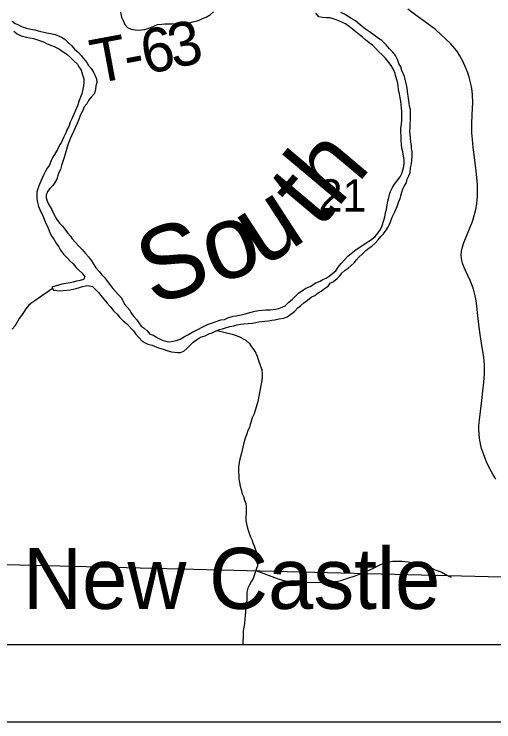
# Model space of a CAD drawing. Extents: x -7.9 to 76.1, y 0 to 22.
# Drawn here: x 7.274 to 7.895, y 14 to 14.915 of the extents above; entities that cross this region are included whole.
import ezdxf

# ---------------------------------------------------------------- set-up
doc = ezdxf.new("R2010")
doc.units = 0
for name, color, linetype in [('GM_X_Major_River', 7, 'Continuous'), ('GM_X_Major_River_Text', 7, 'Continuous'), ('GM_X_Minor_River', 7, 'Continuous'), ('GM_X_Section', 7, 'Continuous'), ('GM_X_Section_Text', 7, 'Continuous'), ('GM_X_State_Route', 7, 'Continuous'), ('GM_X_Township_Road_Text', 7, 'Continuous'), ('GM_X_Unincorporated_Text', 7, 'Continuous'), ('SC_Scratch1', 7, 'Continuous'), ('SH_Data', 7, 'Continuous')]:
    doc.layers.add(name, color=color, linetype=linetype)

msp = doc.modelspace()

# ---------------------------------------------------------------- linework, layer by layer
at = {"layer": 'GM_X_Major_River'}
for points in [[(7.6757, 14.56021), (7.68021, 14.56331), (7.68281, 14.56714), (7.68733, 14.56948), (7.69183, 14.57334), (7.69558, 14.5768), (7.69856, 14.58064), (7.7023, 14.58411), (7.70606, 14.58681), (7.71018, 14.59029), (7.71393, 14.59376), (7.71691, 14.59759), (7.72065, 14.60144), (7.7244, 14.60491), (7.72926, 14.60952), (7.73301, 14.61261), (7.73677, 14.61532), (7.74164, 14.61956), (7.745, 14.6234), (7.74836, 14.62762), (7.7521, 14.63109), (7.75545, 14.63569), (7.75842, 14.64067), (7.761, 14.64639), (7.76283, 14.65135), (7.76467, 14.65517), (7.76651, 14.65937), (7.76945, 14.66662), (7.77202, 14.67273), (7.77348, 14.67655), (7.77457, 14.68036), (7.77565, 14.68493), (7.77711, 14.68912), (7.77895, 14.69294), (7.78154, 14.69753), (7.78262, 14.70172), (7.78484, 14.70592), (7.7863, 14.7105), (7.78698, 14.7162), (7.78804, 14.72153), (7.78874, 14.72647), (7.78904, 14.73179), (7.78897, 14.7371), (7.78816, 14.74126), (7.7881, 14.74543), (7.78728, 14.74998), (7.78684, 14.7549), (7.78596, 14.76362), (7.78628, 14.76818), (7.78659, 14.77349), (7.78691, 14.77767), (7.78672, 14.79171), (7.78552, 14.79625), (7.78509, 14.80042), (7.78425, 14.80648), (7.78341, 14.81178), (7.78299, 14.81557), (7.78256, 14.81935), (7.78174, 14.8239), (7.77894, 14.83448), (7.77737, 14.83826), (7.7758, 14.84241), (7.77422, 14.84694), (7.77188, 14.85146), (7.7703, 14.85637), (7.76758, 14.86165), (7.76411, 14.86577), (7.75988, 14.87027), (7.75526, 14.87552), (7.74987, 14.88113), (7.74529, 14.88373), (7.74145, 14.88671), (7.73532, 14.89156), (7.73112, 14.89416), (7.72691, 14.89713), (7.7223, 14.90086), (7.71578, 14.90647), (7.7112, 14.90906), (7.70164, 14.915), (7.69668, 14.9172)], [(7.70585, 14.60199), (7.71673, 14.61087), (7.72913, 14.61901), (7.73289, 14.62172), (7.73666, 14.62367), (7.74116, 14.62753), (7.74451, 14.63175), (7.74711, 14.63558), (7.74934, 14.6394), (7.75298, 14.65008), (7.75406, 14.65465), (7.75476, 14.65883), (7.75585, 14.66264), (7.7569, 14.66873), (7.7576, 14.67329), (7.75867, 14.67824), (7.75976, 14.68205), (7.76122, 14.68586), (7.76381, 14.69083), (7.76641, 14.69542), (7.76939, 14.69926), (7.77348, 14.70463), (7.7757, 14.70921), (7.77678, 14.7134), (7.77823, 14.71798), (7.77855, 14.72291), (7.77887, 14.72709), (7.77767, 14.73163), (7.77684, 14.73693), (7.77564, 14.74184), (7.77474, 14.75208), (7.77453, 14.76763), (7.77522, 14.77258), (7.77553, 14.77789), (7.77585, 14.78245), (7.77576, 14.78928), (7.77532, 14.79383), (7.77489, 14.79762), (7.77444, 14.80254), (7.77362, 14.80709), (7.7728, 14.81201), (7.77158, 14.81768), (7.77115, 14.82185), (7.77033, 14.82601), (7.76914, 14.83017), (7.76794, 14.83471), (7.76713, 14.83849), (7.76479, 14.84339), (7.76206, 14.84867), (7.75897, 14.8528), (7.75435, 14.85805), (7.75051, 14.86217), (7.74551, 14.86703), (7.74166, 14.87115), (7.73782, 14.87489), (7.73361, 14.87825), (7.72863, 14.88198), (7.72479, 14.88534), (7.72096, 14.88832), (7.71674, 14.89168), (7.71176, 14.89578), (7.70754, 14.89914), (7.70294, 14.90249), (7.69875, 14.90433), (7.69493, 14.90618), (7.69074, 14.90763), (7.68693, 14.9091), (7.68237, 14.91017), (7.67819, 14.91049), (7.67288, 14.9108), (7.66831, 14.91188), (7.66446, 14.91638)], [(7.27139, 14.90601), (7.27522, 14.90302), (7.27979, 14.90119), (7.28361, 14.89935), (7.29009, 14.89716), (7.29579, 14.89572), (7.30073, 14.89503), (7.3053, 14.89357), (7.31595, 14.89106), (7.32127, 14.89), (7.32698, 14.88894), (7.33155, 14.88711), (7.33613, 14.88489), (7.33996, 14.88229), (7.34495, 14.8778), (7.34879, 14.87406), (7.35226, 14.86994), (7.35725, 14.86545), (7.36071, 14.8617), (7.3638, 14.85795), (7.36804, 14.8527), (7.37037, 14.84855), (7.37383, 14.84481), (7.37693, 14.83992), (7.38084, 14.83162), (7.3809, 14.82669), (7.37982, 14.8225), (7.37912, 14.81794), (7.37806, 14.81261), (7.37357, 14.80762), (7.37022, 14.8034), (7.368, 14.79919), (7.36464, 14.79535), (7.36355, 14.79154), (7.36133, 14.78772), (7.35948, 14.7839), (7.35766, 14.77894), (7.35545, 14.7736), (7.35287, 14.76825), (7.35066, 14.76328), (7.34846, 14.75794), (7.34661, 14.75412), (7.34405, 14.74764), (7.34187, 14.74002), (7.34006, 14.73392), (7.33824, 14.72858), (7.33715, 14.72477), (7.33533, 14.71943), (7.33388, 14.7141), (7.33204, 14.71028), (7.33057, 14.70647), (7.32912, 14.7019), (7.32652, 14.69731), (7.32392, 14.69348), (7.32018, 14.68963), (7.3172, 14.68579), (7.31537, 14.68122), (7.31542, 14.67742), (7.31698, 14.67365), (7.31856, 14.66949), (7.32282, 14.66272), (7.32479, 14.65744), (7.32711, 14.65368), (7.32944, 14.64953), (7.33254, 14.64464), (7.33676, 14.64091), (7.34371, 14.6319), (7.34679, 14.62815)], [(7.27345, 14.89313), (7.27805, 14.88978), (7.28302, 14.88719), (7.28949, 14.88539), (7.29442, 14.88469), (7.29899, 14.88362), (7.3028, 14.88253), (7.30699, 14.88108), (7.31194, 14.87925), (7.31576, 14.87702), (7.3211, 14.8752), (7.32567, 14.87336), (7.33255, 14.86966), (7.33637, 14.86706), (7.34211, 14.86334), (7.34709, 14.85924), (7.35171, 14.85437), (7.35593, 14.85063), (7.35788, 14.84687), (7.36059, 14.84273), (7.36256, 14.83669), (7.36415, 14.8314), (7.3642, 14.8276), (7.3639, 14.82228), (7.36281, 14.81809), (7.36176, 14.81201), (7.35808, 14.80361), (7.3559, 14.79675), (7.35296, 14.7895), (7.35039, 14.78377), (7.34854, 14.77995), (7.34671, 14.77537), (7.34488, 14.77004), (7.34266, 14.76621), (7.34119, 14.7624), (7.33824, 14.75628), (7.3353, 14.74979), (7.3327, 14.74558), (7.33012, 14.74023), (7.32752, 14.73564), (7.32418, 14.73029), (7.32197, 14.72608), (7.31977, 14.71998), (7.3168, 14.71576), (7.31457, 14.71194), (7.31235, 14.70773), (7.30977, 14.70239), (7.3061, 14.69323), (7.30464, 14.68904), (7.30356, 14.68523), (7.30323, 14.68105), (7.3033, 14.67612), (7.30412, 14.67157), (7.30571, 14.66628), (7.30727, 14.66251), (7.31157, 14.65346), (7.31314, 14.64893)], [(7.31314, 14.64893), (7.31549, 14.64365), (7.31744, 14.6395), (7.3194, 14.63498), (7.32175, 14.6297), (7.32523, 14.62405), (7.32873, 14.61803), (7.33181, 14.61428), (7.33414, 14.61014), (7.33801, 14.60488), (7.34301, 14.59963), (7.34647, 14.59589), (7.35031, 14.59215), (7.35378, 14.58802), (7.35762, 14.58428), (7.36184, 14.58054), (7.3657, 14.57566), (7.36386, 14.57184), (7.35932, 14.57064), (7.35478, 14.56982), (7.35063, 14.56862), (7.34647, 14.56781), (7.33587, 14.56614), (7.33134, 14.56456), (7.32719, 14.56337), (7.32266, 14.56217), (7.32498, 14.5584), (7.32878, 14.5577), (7.33334, 14.55738), (7.3375, 14.55782), (7.34659, 14.5587), (7.35037, 14.55951), (7.35453, 14.56033), (7.35869, 14.56152), (7.36246, 14.56309), (7.36624, 14.56391), (7.37002, 14.56433), (7.37535, 14.56289), (7.38304, 14.55541), (7.38613, 14.55128), (7.38998, 14.5464), (7.39422, 14.54152), (7.39845, 14.53703), (7.40308, 14.53102), (7.40692, 14.52766), (7.41039, 14.52315), (7.41539, 14.51829), (7.4196, 14.51493), (7.42845, 14.50557), (7.43116, 14.50181), (7.43539, 14.49694), (7.43962, 14.49244), (7.44345, 14.49022), (7.44726, 14.48837), (7.45259, 14.48693), (7.46098, 14.48363), (7.46669, 14.48181), (7.47279, 14.47962), (7.47773, 14.47855), (7.48153, 14.47822), (7.48571, 14.47752), (7.4895, 14.47757), (7.49364, 14.47952), (7.49739, 14.48299), (7.50188, 14.48723), (7.50562, 14.49108), (7.51013, 14.49417), (7.5154, 14.49728), (7.52106, 14.49926), (7.52595, 14.5016), (7.5301, 14.50318), (7.53613, 14.50592), (7.53991, 14.50749), (7.54369, 14.5083), (7.54746, 14.50949), (7.55313, 14.51108), (7.55842, 14.51229), (7.56258, 14.51349), (7.56711, 14.51431), (7.57128, 14.51475), (7.58264, 14.51566), (7.5868, 14.51648), (7.59058, 14.51729), (7.59854, 14.51816), (7.6027, 14.5186), (7.60762, 14.51943), (7.61141, 14.51986), (7.61708, 14.52108), (7.62237, 14.52191), (7.62728, 14.52387), (7.63216, 14.52735), (7.63666, 14.53083), (7.64115, 14.53545), (7.6449, 14.53854), (7.64903, 14.54163), (7.65353, 14.54548), (7.65841, 14.54935), (7.66293, 14.55131), (7.66743, 14.55478), (7.6712, 14.55673), (7.6757, 14.56021)], [(7.34679, 14.62815), (7.34912, 14.62438), (7.35335, 14.61989), (7.35835, 14.61464), (7.36219, 14.6109), (7.36644, 14.60565), (7.37029, 14.60115), (7.37414, 14.59627), (7.37647, 14.5925), (7.37995, 14.58724), (7.38419, 14.58237), (7.38766, 14.57824), (7.39112, 14.57449), (7.39498, 14.56923), (7.40193, 14.56022), (7.4054, 14.55648), (7.40848, 14.55273), (7.41233, 14.5486), (7.41465, 14.54484), (7.41699, 14.53994), (7.42045, 14.53619), (7.42354, 14.53244), (7.42549, 14.52867), (7.42896, 14.52417), (7.43281, 14.51967), (7.43552, 14.51591), (7.43861, 14.51178), (7.44243, 14.50917), (7.44628, 14.50543), (7.44974, 14.50131), (7.45431, 14.49985), (7.4589, 14.49688), (7.4631, 14.49504), (7.46692, 14.4932), (7.47187, 14.49175), (7.47566, 14.49142), (7.47944, 14.49223), (7.4836, 14.49305), (7.48888, 14.49502), (7.49453, 14.49813), (7.49867, 14.50046), (7.50394, 14.50357), (7.50808, 14.50553), (7.51185, 14.50748), (7.5175, 14.51021), (7.52503, 14.51411), (7.52956, 14.51569), (7.53409, 14.51727), (7.54164, 14.51965), (7.54618, 14.52047), (7.5507, 14.52243), (7.5575, 14.52442), (7.56128, 14.52523), (7.56771, 14.52646), (7.573, 14.52767), (7.58056, 14.52968), (7.58547, 14.53088), (7.59077, 14.53172), (7.59986, 14.5326), (7.60517, 14.53267), (7.61274, 14.53354), (7.61652, 14.53435), (7.62066, 14.5363), (7.62481, 14.53788), (7.62968, 14.54288), (7.63417, 14.54673), (7.63791, 14.55058), (7.64203, 14.55443), (7.65143, 14.56063), (7.65709, 14.56299), (7.66461, 14.56765), (7.66988, 14.57), (7.67365, 14.57194), (7.67779, 14.5739), (7.68155, 14.57623), (7.68643, 14.58009), (7.69018, 14.58318), (7.69353, 14.58816), (7.69726, 14.59276), (7.70137, 14.59737), (7.70585, 14.60199)]]:
    msp.add_lwpolyline(points, dxfattribs=at)
at = {"layer": 'GM_X_Minor_River'}
for points in [[(7.41152, 14.91781), (7.41313, 14.91138), (7.41508, 14.90685), (7.41743, 14.90195), (7.42089, 14.89782), (7.42548, 14.89561), (7.43079, 14.89493), (7.43459, 14.8946), (7.43876, 14.89466), (7.4433, 14.8951), (7.44707, 14.89667), (7.45085, 14.89786), (7.45575, 14.89982), (7.45952, 14.90177), (7.4652, 14.90223), (7.46898, 14.90266), (7.47808, 14.90279), (7.48225, 14.90285), (7.49628, 14.90304), (7.50044, 14.90386), (7.50535, 14.90506), (7.50951, 14.90626), (7.51329, 14.90745), (7.51781, 14.90941), (7.52271, 14.91137), (7.52797, 14.91486), (7.5321, 14.91796)], [(7.32375, 14.56039), (7.3009, 14.54441), (7.29715, 14.5417), (7.29302, 14.53861), (7.28929, 14.53401), (7.28632, 14.52941), (7.28371, 14.52558), (7.28074, 14.52137), (7.27851, 14.51754), (7.2748, 14.5118), (7.27144, 14.50758)], [(7.53626, 14.50597), (7.5563, 14.50126), (7.5601, 14.50018), (7.56468, 14.49834), (7.57384, 14.49354), (7.57845, 14.48904), (7.58116, 14.48491), (7.58425, 14.48116), (7.58696, 14.47664), (7.58853, 14.47287), (7.58972, 14.46871), (7.59445, 14.45512), (7.5949, 14.45019), (7.59496, 14.44601), (7.59464, 14.44146), (7.59356, 14.43689), (7.58932, 14.41406), (7.58824, 14.40987), (7.5846, 14.39844), (7.58165, 14.39233), (7.58094, 14.38852), (7.57948, 14.38433), (7.5784, 14.38052), (7.57655, 14.3767), (7.57473, 14.37098), (7.57289, 14.36679), (7.57146, 14.36069), (7.57002, 14.35498), (7.56931, 14.35118), (7.56822, 14.34737), (7.5664, 14.34203), (7.5657, 14.33747), (7.56463, 14.3329), (7.5643, 14.32872), (7.56439, 14.32265), (7.56482, 14.31848), (7.56488, 14.31393), (7.5657, 14.30939), (7.56652, 14.30484), (7.56772, 14.30031), (7.56893, 14.29501), (7.57088, 14.29124), (7.57208, 14.28671), (7.57365, 14.28218), (7.57408, 14.27839), (7.57421, 14.26891), (7.57389, 14.26473), (7.57395, 14.25979), (7.57557, 14.25223), (7.57677, 14.24807), (7.57834, 14.24392), (7.57992, 14.23939), (7.58148, 14.23561), (7.58306, 14.23146), (7.58462, 14.22769), (7.58581, 14.22391), (7.58777, 14.219), (7.58897, 14.21447), (7.58942, 14.20954), (7.58876, 14.20194), (7.58768, 14.19813), (7.58621, 14.19432), (7.58512, 14.19051), (7.5833, 14.18555), (7.58107, 14.18173), (7.57848, 14.17714), (7.57664, 14.17294), (7.5752, 14.16761), (7.57526, 14.16305), (7.57494, 14.15812), (7.57462, 14.15432), (7.57394, 14.14824), (7.57363, 14.14292), (7.57295, 14.13684), (7.57263, 14.13304), (7.57195, 14.12696), (7.57056, 14.11783), (7.57024, 14.1129), (7.5703, 14.10873), (7.56998, 14.10455), (7.57004, 14.1)], [(7.58672, 14.19563), (7.61096, 14.18669), (7.61554, 14.18486), (7.62429, 14.18232), (7.62809, 14.18162), (7.63304, 14.18055), (7.63722, 14.17947), (7.6429, 14.1803), (7.6683, 14.18065), (7.67209, 14.18033), (7.68044, 14.18044), (7.68839, 14.18131), (7.69293, 14.18213), (7.69822, 14.18335), (7.70313, 14.18493), (7.70728, 14.18613), (7.71294, 14.1881), (7.71672, 14.18929), (7.72087, 14.19087), (7.72464, 14.19244), (7.72879, 14.19401), (7.73444, 14.19675), (7.73821, 14.19832), (7.74725, 14.203), (7.75215, 14.20496), (7.75593, 14.20615), (7.76349, 14.20778), (7.77562, 14.20794), (7.77942, 14.20724), (7.78398, 14.20692), (7.78892, 14.20585), (7.79349, 14.2044), (7.7973, 14.20293), (7.80149, 14.20185), (7.80567, 14.20077), (7.80948, 14.19969), (7.81442, 14.19862), (7.819, 14.19678), (7.82281, 14.19532), (7.82739, 14.19348), (7.83197, 14.19089), (7.83579, 14.18867), (7.8396, 14.1872)]]:
    msp.add_lwpolyline(points, dxfattribs=at)
at = {"layer": 'GM_X_Section'}
msp.add_lwpolyline([(7.19836, 15.20958), (8.22746, 15.17634), (8.19936, 14.17955), (7.17682, 14.20532)], close=True, dxfattribs=at)
at = {"layer": 'GM_X_State_Route'}
msp.add_lwpolyline([(7.89744, 14.31394), (7.89328, 14.32046), (7.88923, 14.32787), (7.88517, 14.33639), (7.88162, 14.3453), (7.87896, 14.35359), (7.87802, 14.35719), (7.87693, 14.36215), (7.87668, 14.36364), (7.87612, 14.36715), (7.87562, 14.37208), (7.87535, 14.37854), (7.87544, 14.38275), (7.87583, 14.38729), (7.8766, 14.39393), (7.87931, 14.41547), (7.8807, 14.42796), (7.88175, 14.43928), (7.88251, 14.45), (7.88276, 14.4555), (7.88268, 14.46158), (7.88243, 14.46652), (7.88177, 14.47145), (7.8798, 14.48386), (7.87693, 14.50104), (7.87536, 14.51378), (7.8738, 14.52932), (7.87289, 14.53754), (7.87191, 14.54469), (7.87068, 14.55094), (7.86936, 14.5562), (7.86838, 14.55965), (7.86681, 14.56409), (7.86393, 14.57083), (7.85794, 14.58373), (7.85588, 14.58851), (7.85431, 14.59294), (7.85341, 14.5964), (7.85292, 14.59952), (7.85267, 14.60305), (7.85292, 14.60848), (7.85366, 14.61234), (7.85549, 14.61839), (7.8641, 14.6396), (7.86692, 14.64703), (7.86887, 14.65303), (7.87107, 14.66073), (7.87155, 14.66297), (7.87271, 14.66972), (7.8733, 14.67482), (7.87363, 14.67994), (7.87371, 14.68388), (7.87363, 14.68912), (7.87347, 14.69438), (7.87256, 14.70391), (7.87166, 14.71189), (7.86879, 14.73663), (7.86805, 14.74288), (7.86714, 14.75291), (7.8664, 14.76154), (7.86615, 14.77428), (7.86722, 14.79384), (7.86739, 14.80067), (7.86722, 14.81111), (7.86681, 14.8153), (7.86624, 14.819), (7.86509, 14.82517), (7.8627, 14.8338), (7.8609, 14.83905), (7.85769, 14.84744), (7.85407, 14.85509), (7.85079, 14.86125), (7.84758, 14.86635), (7.84437, 14.87062), (7.83868, 14.87709), (7.82609, 14.88903), (7.81933, 14.89522), (7.81297, 14.89989), (7.79371, 14.91363), (7.78367, 14.92173)], dxfattribs=at)
at = {"layer": 'SC_Scratch1'}
msp.add_lwpolyline([(7.17455, 14.1), (8.19719, 14.1), (8.19936, 14.17955), (7.17682, 14.20532)], close=True, dxfattribs=at)
at = {"layer": 'SH_Data'}
for p, q in [((2.1, 14.1), (8.9, 14.1)), ((2, 14), (9, 14))]:
    msp.add_line(p, q, dxfattribs=at)

# ---------------------------------------------------------------- texts
at = {"layer": 'GM_X_Major_River_Text'}
for s, height, rotation, p in [('th', 0.09469, 49.99287, (7.66903, 14.63597)), ('u', 0.09469, 32.99435, (7.59589, 14.58674)), ('So', 0.094695, 18.99582, (7.45344, 14.53742))]:
    msp.add_text(s, height=height, rotation=rotation, dxfattribs=at).set_placement(p)
at = {"layer": 'GM_X_Section_Text'}
msp.add_text('21', height=0.041856, rotation=0.00001, dxfattribs=at).set_placement((7.66774, 14.65979))
at = {"layer": 'GM_X_Township_Road_Text'}
for s, rotation, p in [('6', 11.22344, (7.44413, 14.83725)), ('3', 13.12648, (7.48048, 14.8445)), ('T', 10.58332, (7.37875, 14.82497)), ('-', 10.71672, (7.42067, 14.83281))]:
    msp.add_text(s, height=0.05682, rotation=rotation, dxfattribs=at).set_placement(p)
at = {"layer": 'GM_X_Unincorporated_Text'}
msp.add_text('New Castle', height=0.078977, rotation=0.00001, dxfattribs=at).set_placement((7.28565, 14.14604))

doc.saveas('drawing.dxf')
